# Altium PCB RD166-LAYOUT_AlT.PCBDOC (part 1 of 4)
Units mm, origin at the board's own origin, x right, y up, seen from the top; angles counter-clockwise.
Board outline 88.7 x 59.07 mm, 2 copper layers (TOP, BOTTOM), stack 0 mm thick; 138 components, 120 nets, 706 pads, 0 vias.
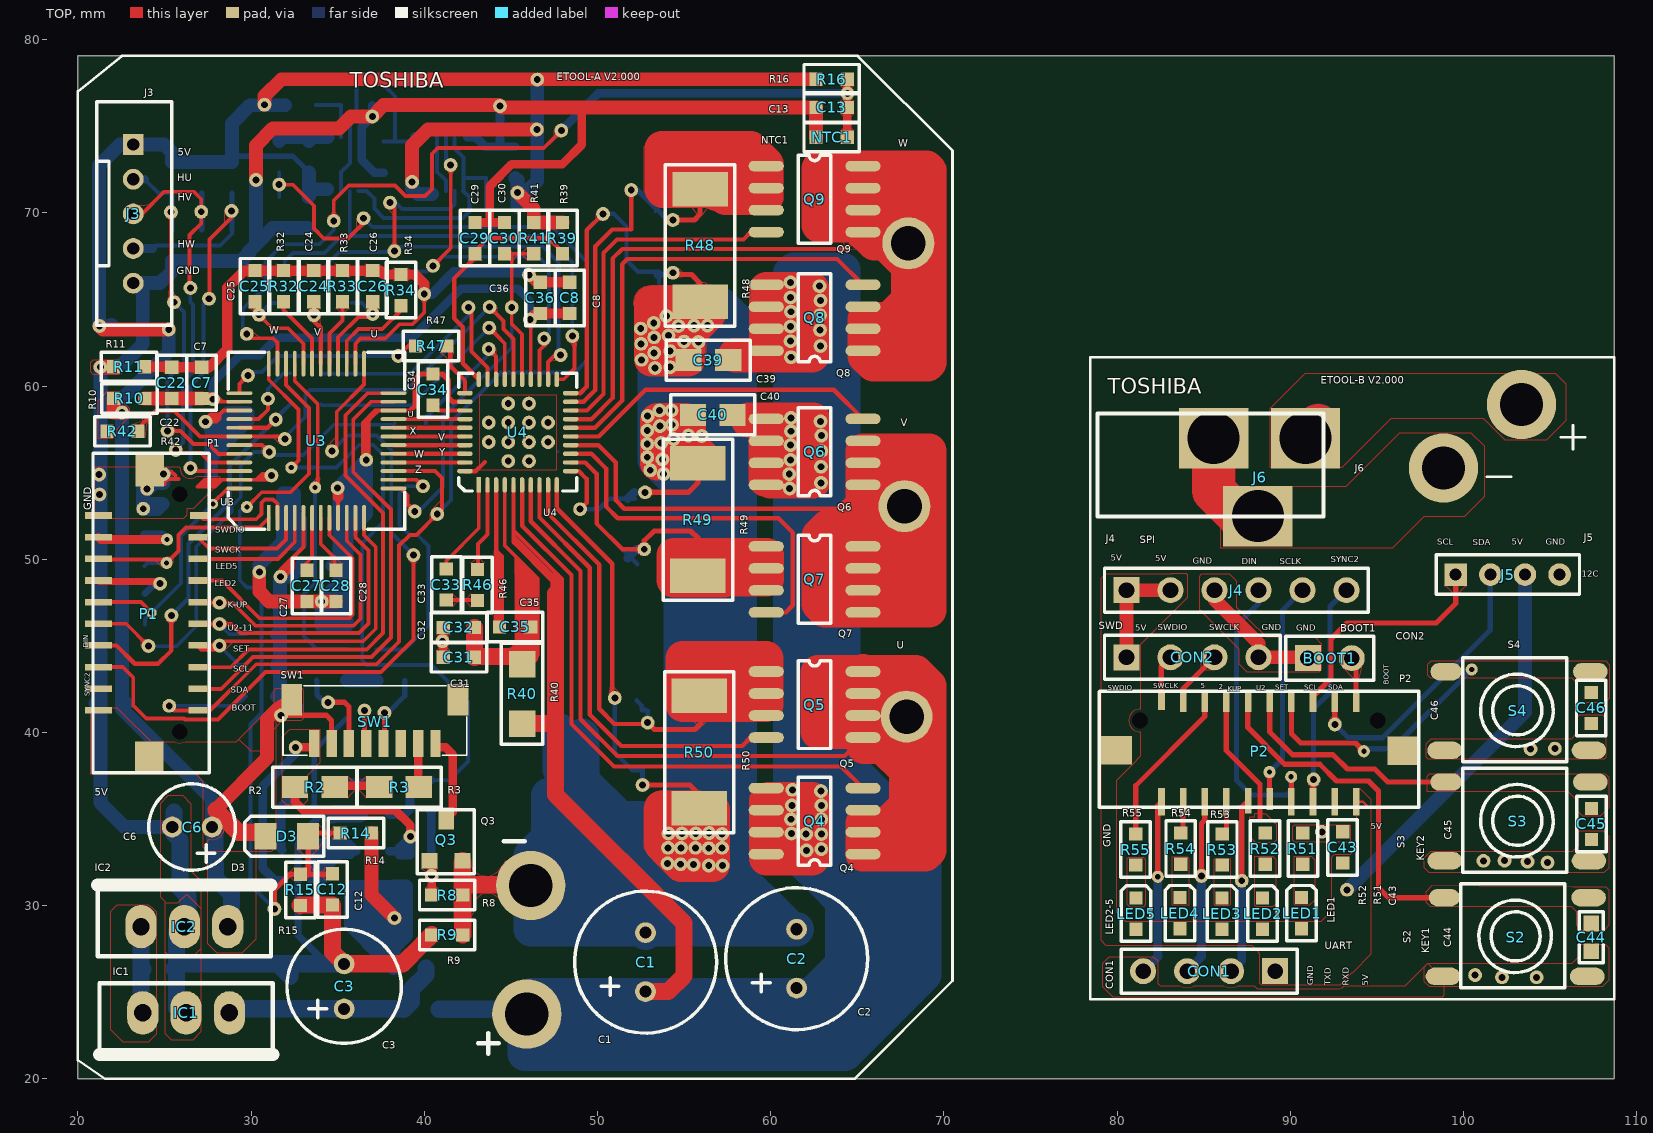
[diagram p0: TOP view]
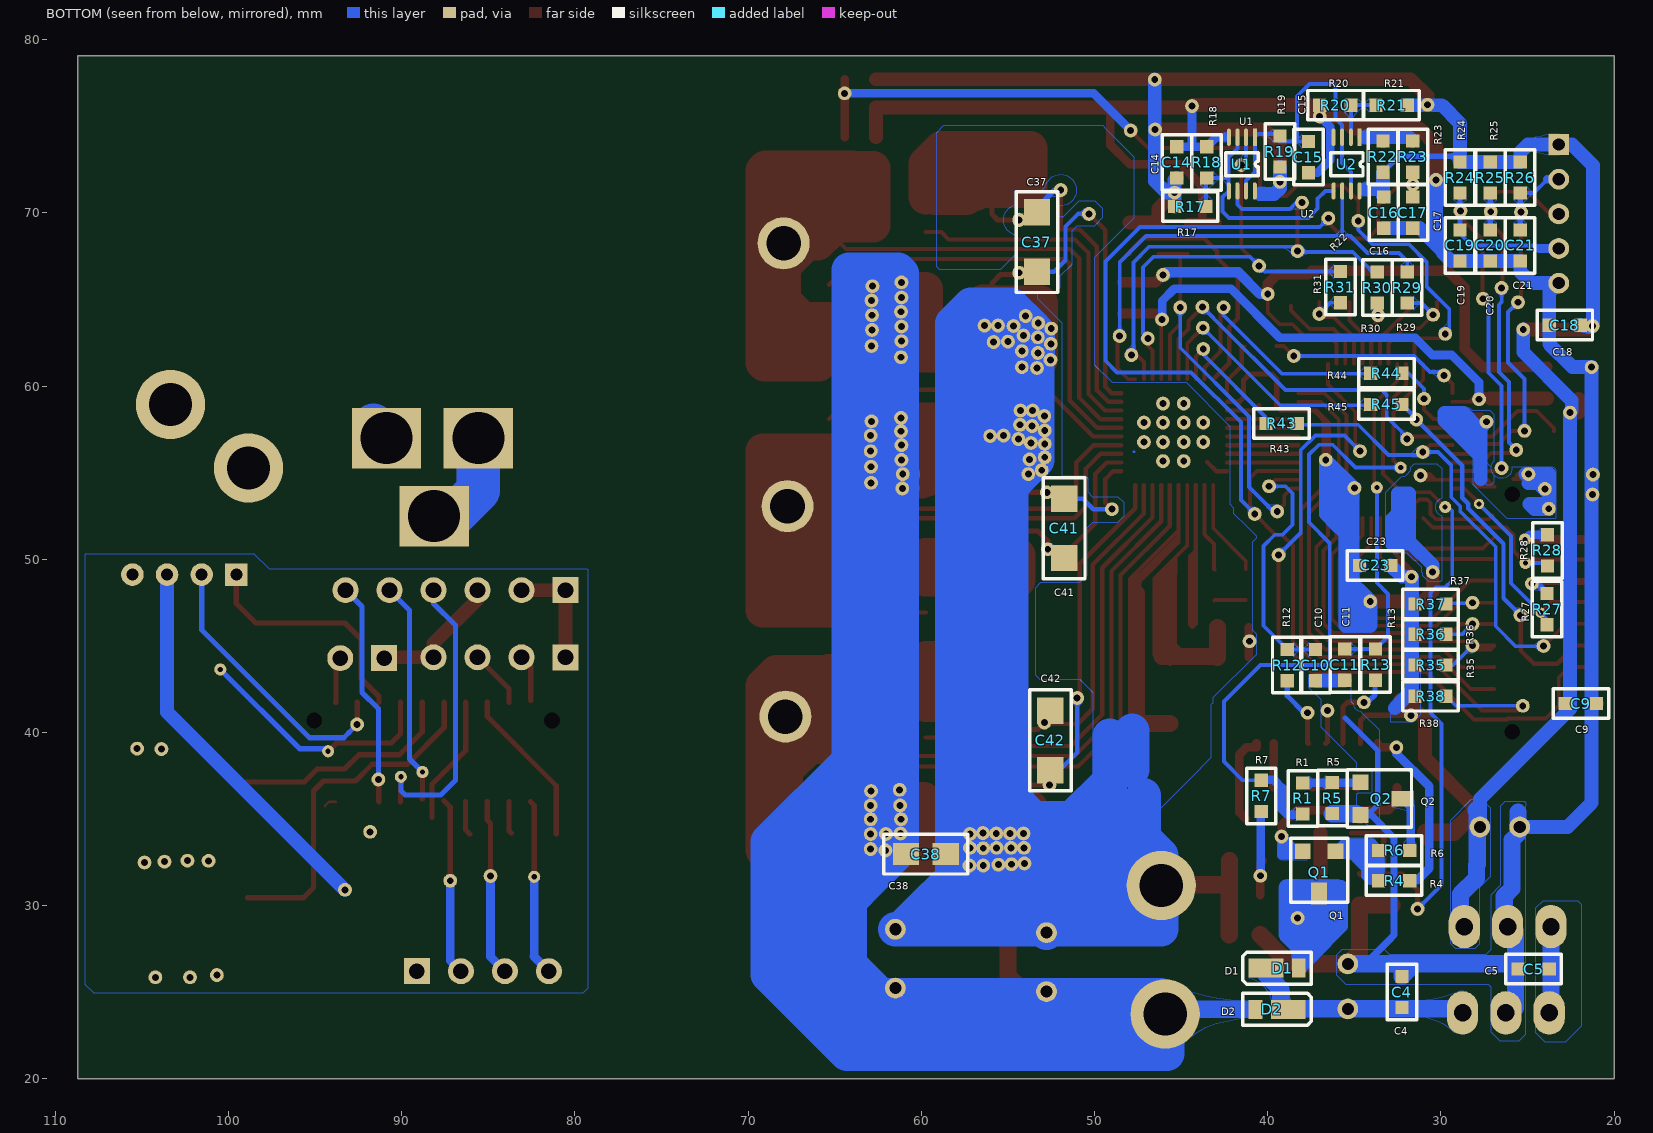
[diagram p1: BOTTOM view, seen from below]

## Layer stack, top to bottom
Top Solder: solder mask 0.0102, Solder Resist, Dk 3.5
TOP: signal copper (thickness not stored)
BOTTOM: signal copper (thickness not stored)
Bottom Solder: solder mask 0.0102, Solder Resist, Dk 3.5

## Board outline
108.7,79.066 108.7,20 20,20 20,79.066

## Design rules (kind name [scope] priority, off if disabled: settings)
AssemblyTestPointUsage [All] p0: scope1count=1 scope1_0_kind=Board scope1_0_value=Board scope2count=1 scope2_0_kind=Board scope2_0_value=Board commentlength=0
AssemblyTestpoint [All] p0: scope1count=1 scope1_0_kind=Board scope1_0_value=Board scope2count=1 scope2_0_kind=Board scope2_0_value=Board commentlength=0
Clearance [All] p0: scope1count=1 scope1_0_kind=Board scope1_0_value=Board scope2count=1 scope2_0_kind=Board scope2_0_value=Board commentlength=0 gap=0.001
Clearance [All] p1: gap=0.001 ignorepadtopadclearanceinfootprint=TRUE except(0.15: Arc-Arc Arc-Track Arc-SMDPad Arc-THPad Arc-Via Arc-Fill Arc-Poly Arc-Region Arc-Text Track-Track Track-SMDPad Track-THPad Track-Via Track-Fill Track-Poly Track-Region Track-Text SMDPad-SMDPad SMDPad-THPad SMDPad-Via SMDPad-Text THPad-THPad THPad-Via THPad-Text Via-Via Via-Fill Via-Poly Via-Region Via-Text Fill-Fill Fill-Poly Fill-Region Fill-Text Poly-Poly Poly-Region Poly-Text Region-Region Region-Text Text-Text; 0.2: SMDPad-Fill SMDPad-Poly SMDPad-Region THPad-Fill THPad-Poly THPad-Region; 0.3: Arc-Hole Track-Hole SMDPad-Hole THPad-Hole Via-Hole Fill-Hole Poly-Hole Region-Hole Text-Hole)
ComponentClearance [All] p0: scope1count=1 scope1_0_kind=Board scope1_0_value=Board scope2count=1 scope2_0_kind=Board scope2_0_value=Board commentlength=0 gap=0.254 collisioncheckmode=3
DiffPairsRouting [All] p0: scope1count=1 scope1_0_kind=Board scope1_0_value=Board scope2count=1 scope2_0_kind=Board scope2_0_value=Board commentlength=0
FabricationTestPointUsage [All] p0: scope1count=1 scope1_0_kind=Board scope1_0_value=Board scope2count=1 scope2_0_kind=Board scope2_0_value=Board commentlength=0 valid=0 allowmultiple=FALSE
FabricationTestpoint [All] p0: scope1count=1 scope1_0_kind=Board scope1_0_value=Board scope2count=1 scope2_0_kind=Board scope2_0_value=Board commentlength=0 side=3 testpointundercomponent=TRUE minsize=1.016 maxsize=2.54 preferedsize=1.524 minholesize=0 maxholesize=1.016 preferedholesize=0.813 testpointgrid=0.025
FanoutControl Fanout_Default [All] p0: scope1count=1 scope1_0_kind=Board scope1_0_value=Board scope2count=1 scope2_0_kind=Board scope2_0_value=Board commentlength=30 // Fanout_Default (Default Rule)
FanoutControl Fanout_Small [All] p0 off: scope1count=1 scope1_0_kind=Board scope1_0_value=Board scope2count=1 scope2_0_kind=Board scope2_0_value=Board commentlength=84 // Protel DXP Scope 1 Expression Was: (CompPinCount < 5)   Fanout_Small (Default Rule)
FanoutControl Fanout_SOIC [All] p0 off: scope1count=1 scope1_0_kind=Board scope1_0_value=Board scope2count=1 scope2_0_kind=Board scope2_0_value=Board commentlength=71 // Protel DXP Scope 1 Expression Was: IsSOIC   Fanout_SOIC (Default Rule)
FanoutControl Fanout_LCC [All] p0 off: scope1count=1 scope1_0_kind=Board scope1_0_value=Board scope2count=1 scope2_0_kind=Board scope2_0_value=Board commentlength=69 // Protel DXP Scope 1 Expression Was: IsLCC   Fanout_LCC (Default Rule)
FanoutControl Fanout_BGA [All] p0 off: scope1count=1 scope1_0_kind=Board scope1_0_value=Board scope2count=1 scope2_0_kind=Board scope2_0_value=Board commentlength=69 // Protel DXP Scope 1 Expression Was: IsBGA   Fanout_BGA (Default Rule)
Height [All] p0: scope1count=1 scope1_0_kind=Board scope1_0_value=Board scope2count=1 scope2_0_kind=Board scope2_0_value=Board commentlength=0
HoleSize [All] p0: scope1count=1 scope1_0_kind=Board scope1_0_value=Board scope2count=1 scope2_0_kind=Board scope2_0_value=Board commentlength=0 absolutevalues=TRUE maxlimit=100 minlimit=0.001 maxpercent=80.000 minpercent=20.000
HoleSize [All] p1: absolutevalues=TRUE maxlimit=100 minlimit=0.001 maxpercent=80.000 minpercent=20.000
HoleToHoleClearance [All] p0: scope1count=1 scope1_0_kind=Board scope1_0_value=Board scope2count=1 scope2_0_kind=Board scope2_0_value=Board commentlength=0
HoleToHoleClearance [All] p1: gap=0.4 allowstackedmicrovias=FALSE
LayerPairs [All] p0: scope1count=1 scope1_0_kind=Board scope1_0_value=Board scope2count=1 scope2_0_kind=Board scope2_0_value=Board commentlength=0 enforce=TRUE
MinimumSolderMaskSliver [All] p0: scope1count=1 scope1_0_kind=Board scope1_0_value=Board scope2count=1 scope2_0_kind=Board scope2_0_value=Board commentlength=0
MinimumSolderMaskSliver [All] p1: minsoldermaskwidth=0.1
NetAntennae [All] p0: scope1count=1 scope1_0_kind=Board scope1_0_value=Board scope2count=1 scope2_0_kind=Board scope2_0_value=Board commentlength=0
NetAntennae [All] p1: netantennaetolerance=100
PasteMaskExpansion [All] p0: scope1count=1 scope1_0_kind=Board scope1_0_value=Board scope2count=1 scope2_0_kind=Board scope2_0_value=Board commentlength=0 expansion=0
PlaneClearance [All] p0: scope1count=1 scope1_0_kind=Board scope1_0_value=Board scope2count=1 scope2_0_kind=Board scope2_0_value=Board commentlength=0 clearance=0.001
PlaneClearance [All] p1: clearance=0.001
PlaneConnect [All] p0: scope1count=1 scope1_0_kind=Board scope1_0_value=Board scope2count=1 scope2_0_kind=Board scope2_0_value=Board commentlength=0 planeconnectstyle=Direct reliefexpansion=0.508 reliefentries=4 reliefconductorwidth=0.254 reliefairgap=0.254
PlaneConnect [All] p1: planeconnectstyle=Direct reliefexpansion=0.508 reliefentries=4 reliefconductorwidth=0.254 reliefairgap=0.254
PolygonConnect [All] p0: scope1count=1 scope1_0_kind=Board scope1_0_value=Board scope2count=1 scope2_0_kind=Board scope2_0_value=Board commentlength=0 connectstyle=Direct reliefconductorwidth=0.254 reliefentries=4 polygonreliefangle="90 Angle"
PolygonConnect [All] p1: connectstyle=Direct reliefconductorwidth=0.254 reliefentries=4 polygonreliefangle="90 Angle" airgapwidth=0.254
RoutingCorners [All] p0: scope1count=1 scope1_0_kind=Board scope1_0_value=Board scope2count=1 scope2_0_kind=Board scope2_0_value=Board commentlength=0 cornerstyle=45-Degree minsetback=2.54 maxsetback=2.54
RoutingLayers [All] p0: scope1count=1 scope1_0_kind=Board scope1_0_value=Board scope2count=1 scope2_0_kind=Board scope2_0_value=Board commentlength=0 top layer=Automatic bottom layer=Automatic
RoutingPriority [All] p0: scope1count=1 scope1_0_kind=Board scope1_0_value=Board scope2count=1 scope2_0_kind=Board scope2_0_value=Board commentlength=0
RoutingTopology [All] p0: scope1count=1 scope1_0_kind=Board scope1_0_value=Board scope2count=1 scope2_0_kind=Board scope2_0_value=Board commentlength=0 topology=Shortest
RoutingVias [All] p0: scope1count=1 scope1_0_kind=Board scope1_0_value=Board scope2count=1 scope2_0_kind=Board scope2_0_value=Board commentlength=0 holewidth=0.1 width=0.1 viastyle="Through Hole" minholewidth=0.001 minwidth=0.001 maxholewidth=100 maxwidth=100
RoutingVias [All] p1: holewidth=0.1 width=0.1 viastyle="Through Hole" minholewidth=0.001 minwidth=0.001 maxholewidth=100 maxwidth=100
ShortCircuit [All] p0: scope1count=1 scope1_0_kind=Board scope1_0_value=Board scope2count=1 scope2_0_kind=Board scope2_0_value=Board commentlength=0 allowed=FALSE
ShortCircuit [All] p0: scope1count=1 scope1_0_kind=Board scope1_0_value=Board scope2count=1 scope2_0_kind=Board scope2_0_value=Board commentlength=0 allowed=FALSE
SilkToBoardRegionClearance [All] p0: scope1count=1 scope1_0_kind=Board scope1_0_value=Board scope2count=1 scope2_0_kind=Board scope2_0_value=Board commentlength=0
SilkToSilkClearance [All] p0: scope1count=1 scope1_0_kind=Board scope1_0_value=Board scope2count=1 scope2_0_kind=Board scope2_0_value=Board commentlength=0
SilkToSilkClearance [All] p1: silktosilkclearance=0.001
SilkToSolderMaskClearance [All] p0 off: scope1count=1 scope1_0_kind=Board scope1_0_value=Board scope2count=1 scope2_0_kind=Board scope2_0_value=Board commentlength=44 // Protel DXP Scope 1 Expression Was: IsPad
SilkToSolderMaskClearance [IsPad] p1: minsilkscreentomaskgap=0 clearancetoexposedcopper=TRUE
SolderMaskExpansion [All] p0: scope1count=1 scope1_0_kind=Board scope1_0_value=Board scope2count=1 scope2_0_kind=Board scope2_0_value=Board commentlength=0 expansion=0.001
SolderMaskExpansion [All] p1: expansion=0.001
UnRoutedNet [All] p0: scope1count=1 scope1_0_kind=Board scope1_0_value=Board scope2count=1 scope2_0_kind=Board scope2_0_value=Board commentlength=0
UnpouredPolygon [All] p0: scope1count=1 scope1_0_kind=Board scope1_0_value=Board scope2count=1 scope2_0_kind=Board scope2_0_value=Board commentlength=0
Width [All] p0: scope1count=1 scope1_0_kind=Board scope1_0_value=Board scope2count=1 scope2_0_kind=Board scope2_0_value=Board commentlength=0 maxlimit=1000 minlimit=2539.975 preferedwidth=0
Width [All] p1: maxlimit=1000 minlimit=2539.975 preferedwidth=0 toplayer_minwidth=0 bottomlayer_minwidth=0 minimp=50.000000 maximp=50.000000 favimp=50.000000
22 further rules are at their usual default settings.

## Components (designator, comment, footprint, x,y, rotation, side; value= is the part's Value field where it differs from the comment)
BOOT1 "HDR1X2" HDR1X2 91.01,44.291 r0 top
C1 "RB_2_3" RB_2_3 52.775,26.741 r90 top
C2 "RB_2_3" RB_2_3 61.5,26.941 r90 top
C3 "RB_13_25" RB_13_25 35.375,25.341 r90 top
C4 "0603-1_bk" 0603-1_bk 32.25,25.016 r270 bottom
C5 "0603-1_bk" 0603-1_bk 24.65,26.341 r180 bottom
C6 "RB_1_2" RB_1_2 26.6,34.541 r180 top
C7 "0603-1" 0603-1 27.15,60.191 r90 top
C8 "0603-1" 0603-1 48.4,65.091 r90 top
C9 "0603-1_bk" 0603-1_bk 21.925,41.666 r0 bottom
C10 "0603-1_bk" 0603-1_bk 37.25,43.891 r90 bottom
C11 "0603-1_bk" 0603-1_bk 35.55,43.916 r90 bottom
C12 "0603-1" 0603-1 34.7,30.941 r270 top
C13 "0603-1" 0603-1 63.525,76.091 r180 top
C14 "0603-1_bk" 0603-1_bk 45.25,72.916 r90 bottom
C15 "0603-1_bk" 0603-1_bk 37.65,73.216 r90 bottom
C16 "0603-1_bk" 0603-1_bk 33.3,70.016 r270 bottom
C17 "0603-1_bk" 0603-1_bk 31.625,70.016 r90 bottom
C18 "0603-1_bk" 0603-1_bk 22.85,63.516 r180 bottom
C19 "0603-1_bk" 0603-1_bk 28.9,68.116 r90 bottom
C20 "0603-1_bk" 0603-1_bk 27.15,68.116 r90 bottom
C21 "0603-1_bk" 0603-1_bk 25.425,68.116 r90 bottom
C22 "0603-1" 0603-1 25.425,60.191 r270 top
C23 "0603-1_bk" 0603-1_bk 33.8,49.641 r180 bottom
C24 "0603-1" 0603-1 33.625,65.766 r90 top
C25 "0603-1" 0603-1 30.225,65.766 r90 top
C26 "0603-1" 0603-1 37.025,65.766 r90 top
C27 "0603-1" 0603-1 33.225,48.466 r270 top
C28 "0603-1" 0603-1 34.9,48.466 r270 top
C29 "0603-1" 0603-1 42.925,68.541 r90 top
C30 "0603-1" 0603-1 44.625,68.541 r90 top
C31 "0603-1" 0603-1 42,44.341 r180 top
C32 "0603-1" 0603-1 42,46.066 r180 top
C33 "0603-1" 0603-1 41.275,48.541 r90 top
C34 "0603-1" 0603-1 40.5,59.791 r90 top
C35 "0603-1" 0603-1 45.25,46.091 r180 top
C36 "0603-1" 0603-1 46.7,65.091 r90 top
C37 "1206_bk" 1206_bk 53.325,68.316 r270 bottom
C38 "0805_bk" 0805_bk 59.743,32.978 r180 bottom
C39 "0805" 0805 56.4,61.492 r180 top
C40 "0805" 0805 56.657,58.341 r180 top
C41 "1206_bk" 1206_bk 51.75,51.79 r90 bottom
C42 "1206_bk" 1206_bk 52.55,39.541 r270 bottom
C43 "0603-1" 0603-1 93.025,33.366 r270 top
C44 "R0603" R0603 107.373,28.973 r270 top
C45 "0603-1" 0603-1 107.4,34.716 r270 top
C46 "0603-1" 0603-1 107.375,41.416 r270 top
CON1 "HDR1X4" HDR1X4 89.125,26.216 r180 top
CON2 "HDR1X4" HDR1X4 80.545,44.341 r0 top
D1 "D-0805-2_bk" D-0805-2_bk 40.1,26.391 r180 bottom
D2 "D-0805-2_bk" D-0805-2_bk 38.814,24.016 r0 bottom
D3 "D-0805-1" D-0805-1 32.053,34.016 r180 top
IC1 "TO-220" TO-220 28.75,23.816 r180 top
IC2 "TO-220" TO-220 23.65,28.791 r0 top
J3 "SSIP5-4" SSIP5-4 23.2,73.941 r270 top
J4 "HDR1X6" HDR1X6 80.545,48.216 r0 top
J5 "HDR1X4-2" HDR1X4-2 99.55,49.116 r0 top
J6 "J-3PIN" J-3PIN 90.875,56.991 r270 top
LED1 "D-0603-2" D-0603-2 90.65,29.566 r90 top
LED2 "D-0603-2" D-0603-2 88.4,29.541 r90 top
LED3 "D-0603-2" D-0603-2 86.05,29.541 r90 top
LED4 "D-0603-2" D-0603-2 83.625,29.566 r90 top
LED5 "D-0603-2" D-0603-2 81.1,29.541 r90 top
NTC1 "0603-1" 0603-1 63.525,74.366 r0 top
P1 "PCBCOMPONENT_1" PCBCOMPONENT_1 21.187,52.526 r270 top
P2 "PCBCOMPONENT_2" PCBCOMPONENT_2 82.565,36.003 r0 top
Q1 "SOT-23_bk" SOT-23_bk 36.084,33.139 r180 bottom
Q2 "SOT-23_bk" SOT-23_bk 34.65,37.133 r90 bottom
Q3 "SOT-23" SOT-23 40.307,32.591 r0 top
Q4 "SO-8" SO-8 65.331,32.978 r180 top
Q5 "SO-8" SO-8 59.743,43.519 r0 top
Q6 "SO-8" SO-8 65.331,54.291 r180 top
Q7 "SO-8" SO-8 59.743,50.741 r0 top
Q8 "SO-8" SO-8 65.331,62.035 r180 top
Q9 "SO-8" SO-8 59.743,72.703 r0 top
R1 "0603-1_bk" 0603-1_bk 37.975,36.191 r90 bottom
R2 "0805" 0805 33.682,36.841 r0 top
R3 "0805" 0805 38.55,36.841 r0 top
R4 "0603-1_bk" 0603-1_bk 32.7,31.441 r0 bottom
R5 "0603-1_bk" 0603-1_bk 36.275,36.216 r270 bottom
R6 "0603-1_bk" 0603-1_bk 32.7,33.191 r0 bottom
R7 "0603-1_bk" 0603-1_bk 40.375,36.341 r90 bottom
R8 "0603-1" 0603-1 41.325,30.616 r0 top
R9 "0603-1" 0603-1 41.325,28.316 r180 top
R10 "0603-1" 0603-1 22.975,59.291 r0 top
R11 "0603-1" 0603-1 22.95,61.116 r0 top
R12 "0603-1_bk" 0603-1_bk 38.875,43.891 r270 bottom
R13 "0603-1_bk" 0603-1_bk 33.775,43.916 r270 bottom
R14 "0603-1" 0603-1 36.05,34.191 r0 top
R15 "0603-1" 0603-1 32.85,30.916 r90 top
R16 "0603-1" 0603-1 63.525,77.716 r0 top
R17 "0603-1_bk" 0603-1_bk 44.475,70.366 r180 bottom
R18 "0603-1_bk" 0603-1_bk 43.525,72.916 r270 bottom
R19 "0603-1_bk" 0603-1_bk 39.3,73.541 r270 bottom
R20 "0603-1_bk" 0603-1_bk 36.1,76.216 r180 bottom
R21 "0603-1_bk" 0603-1_bk 32.85,76.216 r180 bottom
R22 "0603-1_bk" 0603-1_bk 33.35,73.241 r90 bottom
R23 "0603-1_bk" 0603-1_bk 31.625,73.241 r270 bottom
R24 "0603-1_bk" 0603-1_bk 28.9,72.041 r270 bottom
R25 "0603-1_bk" 0603-1_bk 27.15,72.041 r270 bottom
R26 "0603-1_bk" 0603-1_bk 25.425,72.041 r270 bottom
R27 "0603-1_bk" 0603-1_bk 23.875,47.116 r90 bottom
R28 "0603-1_bk" 0603-1_bk 23.85,50.516 r90 bottom
R29 "0603-1_bk" 0603-1_bk 31.95,65.691 r90 bottom
R30 "0603-1_bk" 0603-1_bk 33.675,65.691 r270 bottom
R31 "0603-1_bk" 0603-1_bk 35.8,65.716 r270 bottom
R32 "0603-1" 0603-1 31.875,65.766 r270 top
R33 "0603-1" 0603-1 35.275,65.766 r270 top
R34 "0603-1" 0603-1 38.65,65.541 r270 top
R35 "0603-1_bk" 0603-1_bk 30.6,43.891 r180 bottom
R36 "0603-1_bk" 0603-1_bk 30.6,45.666 r180 bottom
R37 "0603-1_bk" 0603-1_bk 30.6,47.416 r180 bottom
R38 "0603-1_bk" 0603-1_bk 30.6,42.091 r0 bottom
R39 "0603-1" 0603-1 47.975,68.541 r270 top
R40 "1206" 1206 45.65,42.23 r270 top
R41 "0603-1" 0603-1 46.325,68.541 r90 top
R42 "0603-1" 0603-1 22.575,57.391 r180 top
R43 "0603-1_bk" 0603-1_bk 39.2,57.841 r180 bottom
R44 "0603-1_bk" 0603-1_bk 33.15,60.741 r180 bottom
R45 "0603-1_bk" 0603-1_bk 33.15,58.941 r180 bottom
R46 "0603-1" 0603-1 43.075,48.516 r90 top
R47 "0603-1" 0603-1 40.4,62.316 r0 top
R48 "2512" 2512 55.925,68.116 r270 top
R49 "2512" 2512 55.8,52.291 r90 top
R50 "2512" 2512 55.875,38.866 r270 top
R51 "0603-1" 0603-1 90.725,33.291 r90 top
R52 "0603-1" 0603-1 88.55,33.291 r90 top
R53 "0603-1" 0603-1 86.075,33.241 r90 top
R54 "0603-1" 0603-1 83.675,33.291 r90 top
R55 "0603-1" 0603-1 81.075,33.241 r90 top
S2 "DOT6X6SMT" DOT6X6SMT 98.895,30.461 r0 top
S3 "DOT6X6SMT" DOT6X6SMT 98.995,37.136 r0 top
S4 "DOT6X6SMT" DOT6X6SMT 98.995,43.511 r0 top
SW1 "SH1_0_SMD_8" SH1_0_SMD_8 33.65,39.366 r0 top
U1 "SSOP8-0_5_bk" SSOP8-0_5_bk 40.75,74.366 r90 bottom
U2 "SSOP8-0_5_bk" SSOP8-0_5_bk 34.7,74.366 r90 bottom
U3 "LQFP-48" LQFP-48 31.025,52.391 r90 top
U4 "QFN-40" QFN-40 43.15,54.291 r90 top

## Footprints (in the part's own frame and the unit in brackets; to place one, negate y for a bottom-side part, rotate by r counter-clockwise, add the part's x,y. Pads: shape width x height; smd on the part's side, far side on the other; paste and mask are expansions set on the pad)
0603-1 [mil] "KC00080BKP"
  rect 30x30 smd paste-37.87 mask+0: 1(-35.43,0) 2(35.43,0)
  silkscreen extent -63,-33 63,33
0603-1_bk [mil] "KC00080BKP"
  rect 30x30 smd paste-37.87 mask+0: 1(35.43,0) 2(-35.43,0)
  silkscreen extent -63,-33 63,33
0805 [mil] "KC00080BKP"
  rect 60x50 smd paste-67.87 mask+0: 1(-45,0.02) 2(45,0.02)
  silkscreen extent -95,-45 95,45
0805_bk [mil] "KC00080BKP"
  rect 60x50 smd paste-67.87 mask+0: 1(45,-0.02) 2(-45,-0.02)
  silkscreen extent -95,-45 95,45
1206 [mil] "KC00080BKP"
  rect 60x60 smd paste-67.87 mask+0: 1(-67.52,0) 2(67.52,0)
  silkscreen extent -115,-47 115,47
1206_bk [mil] "KC00080BKP"
  rect 60x60 smd paste-67.87 mask+0: 1(67.52,0) 2(-67.52,0)
  silkscreen extent -115,-47 115,47
2512 [mm] "KC00080BKP"
  rect 2x3.2 smd paste-3.4 mask+0: 1(-3.25,0) 2(3.25,0)
  silkscreen extent -4.65,-2 4.65,2
D-0603-2 [mil] "KC00080BKP"
  rect 30x30 smd paste-37.87 mask+0: A(-35.43,0) K(35.43,0)
  silkscreen extent -63,-33 63,33
D-0805-1 [mil] "KC00080BKP"
  rect 50x60 smd paste-67.87 mask+0: 1(-48.09,0) 2(48.09,0)
  silkscreen extent -84,-45 96,45
D-0805-2_bk [mm] "KC00080BKP"
  rect 2x1.1 smd paste-2.2 mask+0: 1(0,0)
  rect 0.8x1.1 smd paste-1.3 mask+0: 2(1.886,0)
  silkscreen extent -1.33,-0.93 2.62,0.93
DOT6X6SMT [mm] "KC00080BKP"
  oval 1.8x1 smd paste-2 mask+0: 1(0,0)
  oval 2x1 smd paste-2.2 mask+0: 2(-0.08,-4.54) 3(8.25,-4.54) 4(8.33,0)
  silkscreen extent 0.96,-5.21 6.96,0.79
HDR1X2 [mm] "KC00080BKP"
  rect 1.5x1.5 / inner round 0 / far side rect 1.5x1.5 hole 0.9 paste-1.7 mask+0: 1(0,0)
  round 1.5 / inner round 0 / far side round 1.5 hole 0.9 paste-1.7 mask+0: 2(2.54,0)
  silkscreen extent -1.27,-1.27 3.81,1.27
HDR1X4 [mm] "KC00080BKP"
  rect 1.5x1.5 / inner round 0 / far side rect 1.5x1.5 hole 0.9 paste-1.7 mask+0: 1(0,0)
  round 1.5 / inner round 0 / far side round 1.5 hole 0.9 paste-1.7 mask+0: 2(2.54,0) 3(5.08,0) 4(7.62,0)
  silkscreen extent -1.27,-1.27 8.89,1.27
HDR1X4-2 [mm] "KC00080BKP"
  rect 1.3x1.3 / inner round 0 / far side rect 1.3x1.3 hole 0.7 paste-1.5 mask+0: 1(0,0)
  round 1.3 / inner round 0 / far side round 1.3 hole 0.7 paste-1.5 mask+0: 2(2,0) 3(4,0) 4(6,0)
  silkscreen extent -1.12,-1.13 7.15,1.15
HDR1X6 [mm] "KC00080BKP"
  rect 1.5x1.5 / inner round 0 / far side rect 1.5x1.5 hole 0.9 paste-1.7 mask+0: 1(0,0)
  round 1.5 / inner round 0 / far side round 1.5 hole 0.9 paste-1.7 mask+0: 2(2.54,0) 3(5.08,0) 4(7.62,0) 5(10.16,0) 6(12.7,0)
  silkscreen extent -1.27,-1.27 13.97,1.27
J-3PIN [mm] "KC00080BKP"
  rect 3.5x4 / inner round 0 / far side rect 3.5x4 hole 3 paste-4.2 mask+0: 1(0,0) 2(0,-5.3) 3(4.5,-2.75)
  silkscreen extent -1.42,-12 4.52,1.05
LQFP-48 [mm] "KC00080BKP"
  rect 1.5x0.22 smd paste-1.7 mask+0: 1(0,0)
  oval 1.5x0.22 smd paste-1.7 mask+0: 2(0,-0.5) 3(0,-1) 4(0,-1.5) 5(0,-2) 6(0,-2.5) 7(0,-3) 8(0,-3.5) 9(0,-4) 10(0,-4.5) 11(0,-5) 12(0,-5.5) 25(8.9,-5.5) 26(8.9,-5) 27(8.9,-4.5) 28(8.9,-4) 29(8.9,-3.5) 30(8.9,-3) 31(8.9,-2.5) 32(8.9,-2) 33(8.9,-1.5) 34(8.9,-1) 35(8.9,-0.5) 36(8.9,0)
  oval 0.22x1.5 smd paste-1.7 mask+0: 13(1.7,-7.2) 14(2.2,-7.2) 15(2.7,-7.2) 16(3.2,-7.2) 17(3.7,-7.2) 18(4.2,-7.2) 19(4.7,-7.2) 20(5.2,-7.2) 21(5.7,-7.2) 22(6.2,-7.2) 23(6.7,-7.2) 24(7.2,-7.2) 37(7.2,1.7) 38(6.7,1.7) 39(6.2,1.7) 40(5.7,1.7) 41(5.2,1.7) 42(4.7,1.7) 43(4.2,1.7) 44(3.7,1.7) 45(3.2,1.7) 46(2.7,1.7) 47(2.2,1.7) 48(1.7,1.7)
  silkscreen extent -0.65,-7.85 9.55,2.35
PCBCOMPONENT_1 [mil] "KC00080BKP"
  rect 15x62.01 smd paste-69.88 mask+0: 1(442.91,0) 2(393.7,0) 3(344.49,0) 4(295.28,0) 5(246.06,0) 6(196.85,0) 7(147.64,0) 8(98.43,0) 9(49.21,0) 10(0,0)
  rect 15x43.31 smd paste-51.18 mask+0: 11(442.91,225.91) 12(393.7,225.91) 13(344.49,225.91) 14(295.28,225.91) 15(246.06,225.91) 16(196.85,225.91) 17(147.64,225.91) 18(98.43,225.91) 19(49.21,225.91) 20(0,229.84)
  rect 70.87x64.96 smd paste-78.74 mask+0: 21(548.62,115.67) 22(-101.97,116.65)
  round 3.94 / inner round 0 / far side round 3.94 hole 35.43 unplated paste-43.31 mask+0: 23(491.77,184.57) 24(-48.82,184.57)
  silkscreen extent -141,-12 585,252
PCBCOMPONENT_2 [mm] "KC00080BKP"
  rect 0.381x1.575 smd paste-1.775 mask+0: 1(11.25,0) 2(10,0) 3(8.75,0) 4(7.5,0) 7(3.75,0) 8(2.5,0) 9(1.25,0) 10(0,0)
  rect 0.381x1.275 smd paste-1.475 mask+0: 5(6.25,0.15)
  rect 0.381x1.453 smd paste-1.653 mask+0: 6(5,0.06)
  rect 0.381x1.1 smd paste-1.3 mask+0: 11(11.25,5.738) 12(10,5.738) 13(8.75,5.738) 14(7.5,5.738) 15(6.25,5.738) 16(5,5.738) 17(3.75,5.738) 18(2.5,5.738) 19(1.25,5.738) 20(0,5.838)
  rect 1.8x1.65 smd paste-2 mask+0: 21(13.935,2.938) 22(-2.59,2.963)
  round 0.1 / inner round 0 / far side round 0.1 hole 0.9 unplated paste-1.1 mask+0: 23(12.491,4.688) 24(-1.24,4.688)
  silkscreen extent -3.59,-0.31 14.86,6.39
QFN-40 [mm] "KC00080BKP"
  rect 0.9x0.25 smd paste-1.1 mask+0: 1(0,0)
  oval 0.9x0.25 smd paste-1.1 mask+0: 2(0,-0.5) 3(0,-1) 4(0,-1.5) 5(0,-2) 6(0,-2.5) 7(0,-3) 8(0,-3.5) 9(0,-4) 10(0,-4.5) 21(6.1,-4.5) 22(6.1,-4) 23(6.1,-3.5) 24(6.1,-3) 25(6.1,-2.5) 26(6.1,-2) 27(6.1,-1.5) 28(6.1,-1) 29(6.1,-0.5) 30(6.1,0)
  oval 0.25x0.9 smd paste-1.1 mask+0: 11(0.8,-5.3) 12(1.3,-5.3) 13(1.8,-5.3) 14(2.3,-5.3) 15(2.8,-5.3) 16(3.3,-5.3) 17(3.8,-5.3) 18(4.3,-5.3) 19(4.8,-5.3) 20(5.3,-5.3) 31(5.3,0.8) 32(4.8,0.8) 33(4.3,0.8) 34(3.8,0.8) 35(3.3,0.8) 36(2.8,0.8) 37(2.3,0.8) 38(1.8,0.8) 39(1.3,0.8) 40(0.8,0.8)
  silkscreen extent -0.35,-5.65 6.45,1.15
R0603 [mm] "KC00080BKP"
  rect 0.9x0.9 smd paste-1.1 mask+0: 1(0,0) 2(1.6,0)
  silkscreen extent -0.68,-0.7 2.28,0.7
RB_1_2 [mm] "KC00080BKP"
  round 1.2 / inner round 0 / far side round 1.2 hole 0.7 paste-1.4 mask+0: 1(-1.15,0) 2(1.15,0)
  silkscreen extent -2.5,-2.5 2.5,2.5
RB_2_3 [mm] "KC00080BKP"
  round 1.2 / inner round 0 / far side round 1.2 hole 0.7 paste-1.4 mask+0: 1(-1.7,0) 2(1.7,0)
  silkscreen extent -4.1,-4.1 4.1,4.1
RB_13_25 [mm] "KC00080BKP"
  round 1.2 / inner round 0 / far side round 1.2 hole 0.7 paste-1.4 mask+0: 1(-1.3,0) 2(1.3,0)
  silkscreen extent -3.3,-3.3 3.3,3.3
SH1_0_SMD_8 [mm] "KC00080BKP"
  rect 0.6x1.55 smd paste-1.75 mask+0: 1(0,0) 2(1,0) 3(2,0) 4(3,0) 5(4,0) 6(5,0) 7(6,0) 8(7,0)
  rect 1.2x1.8 smd paste-2 mask+0: 9(8.3,2.525) 10(-1.3,2.525)
  silkscreen extent -1.8,-0.67 8.8,3.33
SO-8 [mil] "KC00080BKP"
  oval 80x24.02 smd paste-87.87 mask+0: 1(0,0) 2(0,-50) 3(0,-100) 4(0,-150) 5(220,-150) 6(220,-100) 7(220,-50) 8(220,0)
  silkscreen extent 73,-175 147,25
SOT-23 [mm] "KC00080BKP"
  rect 0.91x0.91 smd paste-1.11 mask+0: B(0,0) E(1.9,0)
  rect 0.91x1.27 smd paste-1.47 mask+0: C(0.958,2.43)
  silkscreen extent -0.71,-0.75 2.59,2.95
SOT-23_bk [mm] "KC00080BKP"
  rect 0.91x0.91 smd paste-1.11 mask+0: B(0,0) E(-1.9,0)
  rect 0.91x1.27 smd paste-1.47 mask+0: C(-0.958,-2.43)
  silkscreen extent -2.59,-2.95 0.71,0.75
SSIP5-4 [mm] "KC00080BKP"
  rect 1.2x1.2 / inner round 0 / far side rect 1.2x1.2 hole 0.7 paste-1.4 mask+0: 1(0,0)
  round 1.2 / inner round 0 / far side round 1.2 hole 0.7 paste-1.4 mask+0: 2(2,0) 3(4,0) 4(6,0) 5(8,0)
  silkscreen extent -2.47,-2.1 10.42,2.23
SSOP8-0_5_bk [mm] "KC00080BKP"
  rect 1x0.23 smd paste-1.2 mask+0: 1(0,0)
  oval 1x0.23 smd paste-1.2 mask+0: 2(0,0.5) 3(0,1) 4(0,1.5) 5(-3.1,1.5) 6(-3.1,1) 7(-3.1,0.5) 8(-3.1,0)
  silkscreen extent -2.22,-0.2 -0.88,1.68
TO-220 [mm] "KC00080BKP"
  oval 1.8x2.5 / inner round 0 / far side oval 1.8x2.5 hole 1 paste-2.7 mask+0: 1(0,0) 2(2.5,0) 3(5,0)
  silkscreen extent -2.5,-1.7 7.5,2.4

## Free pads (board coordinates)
  round 0.8 / inner round 0 / far side round 0.8 hole 0.4 paste-0.8 mask+0: ""(21.225,54.891) ""(21.25,63.466) ""(21.25,53.741) ""(21.3,61.091) ""(22.55,58.466) ""(23.775,52.916) ""(24,54.066) ""(24.075,44.991) ""(24.751,48.59) ""(24.95,54.916) ""(25.176,57.415) ""(25.25,63.266) ""(25.276,41.54) ""(25.375,70.041) ""(25.401,46.765) ""(25.55,64.841) ""(25.651,56.315) ""(26.5,65.666) ""(26.501,55.265) ""(27.125,70.066) ""(27.375,57.941) ""(27.575,65.041) ""(27.8,59.241) ""(28.176,45.015) ""(28.176,47.49) ""(28.18,46.265) ""(28.875,70.116) ""(29.75,63.016) ""(29.825,60.616) ""(30.287,71.903) ""(30.45,64.116) ""(30.476,49.265) ""(30.775,76.241) ""(30.975,59.266) ""(31.05,56.191) ""(31.176,54.84) ""(31.351,29.815) ""(31.425,58.066) ""(31.625,71.628) ""(31.701,48.99) ""(31.735,40.991) ""(31.951,56.94) ""(32.575,39.141) ""(33.625,64.091) ""(34.084,47.565) ""(34.451,41.742) ""(34.675,56.241) ""(34.775,69.541) ""(35,54.116) ""(36.5,69.691) ""(36.551,41.265) ""(36.65,55.743) ""(37,75.566) ""(37.025,64.166) ""(37.701,41.14) ""(38.025,70.591) ""(38.275,67.791) ""(38.276,29.29) ""(38.5,61.741) ""(39.201,33.99) ""(39.3,71.791) ""(39.375,50.241) ""(39.451,52.765) ""(39.925,54.216) ""(40,65.316) ""(40.426,31.726) ""(40.5,66.941) ""(40.75,52.616) ""(41.05,45.266) ""(41.525,72.766) ""(42.551,64.54) ""(43.725,56.766) ""(43.725,57.891) ""(43.725,62.141) ""(43.75,63.366) ""(43.776,64.565) ""(44.375,76.166) ""(44.85,55.666) ""(44.85,56.766) ""(44.85,57.891) ""(44.85,58.991) ""(45.05,64.541) ""(45.375,71.166) ""(46.05,55.666) ""(46.05,56.766) ""(46.05,57.891) ""(46.05,58.991) ""(46.05,66.416) ""(46.1,63.841) ""(46.5,74.816) ""(46.525,77.691) ""(46.925,62.741) ""(47.15,56.766) ""(47.15,57.891) ""(47.876,61.79) ""(47.912,74.753) ""(48.551,62.89) ""(49.001,52.89) ""(50.325,69.941) ""(51.001,41.99) ""(51.951,71.315) ""(52.5,63.316) ""(52.525,62.441) ""(52.55,61.516) ""(52.6,36.966) ""(52.701,50.578) ""(52.75,53.866) ""(52.875,55.891) ""(52.875,56.666) ""(52.875,57.441) ""(52.9,40.566) ""(52.9,58.266) ""(53.05,55.141) ""(53.25,63.641) ""(53.275,61.916) ""(53.275,62.816) ""(53.325,61.041) ""(53.575,58.591) ""(53.6,57.691) ""(53.675,56.716) ""(53.75,55.766) ""(53.825,54.916) ""(53.975,64.041) ""(54.05,32.441) ""(54.075,33.341) ""(54.1,34.166) ""(54.1,62.916) ""(54.2,61.091) ""(54.2,62.016) ""(54.275,58.591) ""(54.3,57.766) ""(54.35,66.541) ""(54.35,69.591) ""(54.4,56.941) ""(54.675,63.466) ""(54.8,32.391) ""(54.825,33.341) ""(54.875,34.166) ""(55,62.566) ""(55.25,57.141) ""(55.55,32.366) ""(55.575,63.491) ""(55.65,33.341) ""(55.675,34.166) ""(55.825,62.541) ""(56.025,57.116) ""(56.35,63.491) ""(56.425,32.316) ""(56.425,33.316) ""(56.45,34.191) ""(57.2,33.341) ""(57.2,34.141) ""(57.225,32.316) ""(61.075,54.916) ""(61.1,54.091) ""(61.15,55.741) ""(61.15,56.591) ""(61.15,62.591) ""(61.15,63.441) ""(61.15,65.116) ""(61.15,65.991) ""(61.175,34.991) ""(61.175,57.391) ""(61.175,58.166) ""(61.175,61.666) ""(61.175,64.291) ""(61.2,34.166) ""(61.225,35.791) ""(61.25,36.691) ""(62.05,34.141) ""(62.075,33.191) ""(62.825,65.766) ""(62.85,63.241) ""(62.85,64.091) ""(62.875,57.966) ""(62.875,62.316) ""(62.875,64.941) ""(62.9,36.616) ""(62.9,54.416) ""(62.9,55.341) ""(62.925,33.266) ""(62.925,34.141) ""(62.925,34.991) ""(62.925,35.791) ""(62.925,56.241) ""(62.925,57.141) ""(64.425,76.903) ""(84.875,31.716) ""(87.2,31.441) ""(91.351,37.29) ""(91.823,34.266) ""(92.575,40.466) ""(93.275,30.916) ""(100.675,25.991) ""(101.15,32.591) ""(102.225,25.866) ""(102.375,32.598) ""(103.7,32.541) ""(103.875,39.041) ""(104.225,25.866) ""(104.85,32.491) ""(105.275,39.066)
  round 0.6 / inner round 0 / far side round 0.6 hole 0.3 paste-0.6 mask+0: ""(24.251,46.915) ""(27.8,53.192)
  round 0.7 / inner round 0 / far side round 0.7 hole 0.3 paste-0.7 mask+0: ""(25.126,49.79) ""(25.151,51.14) ""(29.758,53.015) ""(32.325,55.291) ""(33.701,54.14) ""(82.351,31.665) ""(88.801,37.715) ""(90.051,37.44) ""(94.25,38.916) ""(100.475,43.641)
  round 4 / inner round 0 / far side round 4 hole 2.5 paste-4.203 mask+0: ""(45.925,23.741) ""(46.15,31.166) ""(98.85,55.266) ""(103.35,58.941)
  round 3 / inner round 0 / far side round 3 hole 2 paste-3.203 mask+0: ""(67.725,53.066) ""(67.85,40.916) ""(67.95,68.241)

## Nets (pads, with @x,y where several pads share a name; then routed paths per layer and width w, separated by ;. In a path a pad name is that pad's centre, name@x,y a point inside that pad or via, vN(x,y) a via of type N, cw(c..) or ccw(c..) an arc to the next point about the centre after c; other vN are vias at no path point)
5V: C7.1 C8.1 C22.2 C36.1 pad.@27.8,59.241 pad.@46.1,63.841 R10.2 U3.38 U4.24 | length 37.1
  TOP w0.127: C7.1@27.15,59.291 27.347,59.094 27.653,59.094 pad.@27.8,59.241
  TOP w0.22: pad.@27.8,59.241 28.226,59.24 ; U3.38@29.325,59.091 28.376,59.09 ; pad.@46.1,63.841 46.151,63.79 46.151,63.092 ; U4.24@46.15,60.391 46.15,63.091 ; 28.226,59.24 27.926,59.54 27.401,59.54 C7.1@27.15,59.291 27.347,59.094 27.351,59.09 28.376,59.09 ; 28.226,59.24 28.376,59.09
  TOP w0.6: pad.@46.1,63.841 46.45,64.191 C36.1@46.7,64.191 C8.1@48.4,64.191
  TOP w0.8: R10.2@23.875,59.291 25.424,59.29 C22.2@25.425,59.291 C7.1@27.15,59.291
  BOTTOM w0.5: pad.@27.8,59.241 27.8,60.216 29.375,61.791 30.5,61.791 31.5,62.791 39.3,62.791 42.125,65.616 45.4,65.616 46.1,64.916 pad.@46.1,63.841
12V: C5.1 IC1.3 IC2.1 | length 5.4
  BOTTOM w1: IC1.3@23.525,23.766 IC1.3@23.65,23.891 ; IC2.1@23.65,28.916 IC2.1@23.65,28.791 C5.1@23.65,26.342 ; IC1.3@23.75,23.816 IC1.3@23.65,23.891 ; C5.1@23.75,26.342 C5.1@23.65,26.342 ; IC1.3@23.65,23.891 C5.1@23.65,26.342
18V: D1.2 pad.@38.276,29.29 Q1.C R14.2 | length 35.4
  TOP w0.8: R14.2@36.95,34.191 36.95,33.283 36.951,33.282 36.951,30.615 pad.@38.276,29.29
  BOTTOM w0.127: Q1.C@37.04,30.711 37.507,30.711 37.751,30.467
  BOTTOM w0.8: Q1.C@37.042,31.109 Q1.C@37.042,31.09 ; Q1.C@37.076,30.24 37.076,27.565 ; pad.@38.276,29.29 pad.@38.215,29.29 ; 38.965,31.101 38.215,31.101 38.215,31.09 ; 36.326,28.315 36.326,30.99 36.426,31.09 ; 36.326,28.315 36.662,27.979 ; 36.326,28.315 35.776,28.865 35.776,31.09 36.426,31.09 ; 36.426,31.09 Q1.C@37.042,31.09 ; 36.662,27.979 36.662,27.943 37.076,27.529 ; 36.662,27.979 37.076,27.565 ; Q1.C@37.042,31.09 37.626,31.09 ; 37.076,27.529 D1.2@38.214,26.391 38.215,27.554 ; 37.076,27.529 37.076,27.565 ; 37.076,27.565 37.112,27.529 37.751,27.529 ; 37.626,31.09 38.215,31.09 ; 37.626,31.09 37.751,30.965 37.751,30.467 37.751,27.529 ; 37.751,27.529 38.19,27.529 38.215,27.554 ; 38.215,27.554 pad.@38.215,29.29 ; 38.215,27.554 38.965,28.304 38.965,31.09 38.215,31.09 ; pad.@38.215,29.29 38.215,31.09
19VDC: J6.1 pad.@103.35,58.941 | length 2.1
  TOP w2.5: J6.1@90.875,56.991 J6.1@91.601,57.715
  BOTTOM w2.5: J6.1@90.875,56.991 J6.1@91.625,57.741
+5V: C6.1 C9.1 C14.2 C16.2 C18.1 C23.1 D3.2 IC2.3 J3.1 P1.1 P1.21 pad.@21.25,63.466 pad.@22.55,58.466 pad.@25.25,63.266 pad.@30.775,76.241 pad.@31.701,48.99 pad.@31.735,40.991 pad.@39.3,71.791 pad.@45.375,71.166 pad.@46.5,74.816 pad.@46.525,77.691 R10.1 R16.1 R17.2 R19.1 R21.1 R22.2 R24.2 R25.2 R26.2 R35.2 R36.2 R37.2 R38.1 R39.1 R41.2 R42.2 SW1.2 SW1.10 U1.8 U2.8 U3.5 | length 173.3
  TOP w0.22: U3.5@33.025,52.391 33.026,50.715 32.388,50.078 ; pad.@31.701,49.103 32.238,49.64 ; pad.@31.701,49.103 31.701,49.39 32.238,49.928 ; pad.@31.701,49.103 pad.@31.701,48.99 31.901,48.99 32.238,49.328 ; 32.238,49.328 32.388,49.478 32.388,50.078 ; 32.238,49.328 32.238,49.64 ; 32.238,49.64 32.238,49.928 ; 32.238,49.928 32.388,50.078
  TOP w0.3: pad.@31.735,40.991 32.351,40.99 ; SW1.10@32.351,41.89 32.351,40.99 ; SW1.2@34.65,39.366 34.651,39.367 34.651,40.69 34.351,40.99 32.351,40.99
  TOP w0.8: pad.@21.25,63.466 21.451,63.265 pad.@25.25,63.266 ; R10.1@22.051,59.267 22.051,58.465 pad.@22.55,58.466 ; 27.976,35.515 27.951,35.54 30.926,38.515 30.926,40.765 31.443,41.283 ; pad.@30.775,76.241 30.776,76.74 ; pad.@31.735,40.991 31.593,41.133 31.443,41.283 ; SW1.10@32.351,41.89 31.51,41.327 31.443,41.283 ; pad.@39.3,71.791 39.3,72.718 ; 39.301,72.719 39.301,73.89 40.226,74.815 pad.@46.5,74.816 ; pad.@45.375,71.166 46.326,70.215 R41.2@46.325,69.441 R39.1@47.975,69.441 ; pad.@46.525,77.691 pad.@46.525,77.691 ; R16.1@62.626,77.714 62.624,77.715 pad.@46.55,77.715 ; 30.776,76.74 31.751,77.715 ; 30.776,76.74 31.751,77.715 ; 31.751,77.715 pad.@46.526,77.715 ; pad.@46.525,77.691 pad.@46.526,77.715 ; pad.@46.525,77.691 pad.@46.55,77.715 ; pad.@46.526,77.715 pad.@46.55,77.715
  TOP w1: C6.1@27.75,34.541 28.351,35.14 ; 27.976,35.515 28.351,35.14 ; D3.2@30.832,34.016 D3.2@30.833,34.24 ; D3.2@30.876,34.24 D3.2@30.833,34.24 ; 28.351,35.14 29.251,34.24 D3.2@30.833,34.24
  BOTTOM w0.127: pad.@21.25,63.466 21.425,63.466 21.708,63.466 21.9,63.466 C18.1@21.95,63.516
  BOTTOM w0.3: R24.2@28.9,72.941 29.225,73.266 32.425,73.266 R22.2@33.35,72.341
  BOTTOM w0.8: C18.1@21.949,63.518 21.708,63.466 21.475,63.416 21.425,63.466 21.337,63.554 pad.@21.225,63.666 ; C9.1@22.825,41.666 C9.1@22.823,41.664 ; C9.1@22.825,41.664 C9.1@22.823,41.664 ; pad.@25.25,63.266 25.25,61.966 22.45,59.166 22.45,58.566 pad.@22.55,58.466 C9.1@22.55,41.664 ; C6.1@27.75,34.541 27.75,36.166 22.55,41.366 C9.1@22.55,41.664 ; R24.2@28.899,72.941 R25.2@27.15,72.941 27.149,72.941 R26.2@25.425,72.941 25.425,73.491 24.975,73.941 J3.1@23.2,73.941 22.425,73.941 21.225,72.741 pad.@21.225,63.666 ; R24.2@28.9,72.941 28.9,75.166 29.95,76.216 30.75,76.216 pad.@30.775,76.241 30.8,76.216 R21.1@31.95,76.216 ; R36.2@31.5,45.666 31.501,45.667 R36.2@31.675,45.667 ; R37.2@31.5,47.416 31.501,47.417 R37.2@31.675,47.417 ; R38.1@31.5,42.091 R38.1@31.737,42.329 ; R35.2@31.5,43.891 R35.2@31.675,43.891 ; 32.669,41.397 R38.1@31.737,42.329 ; C23.1@32.9,49.641 32.25,48.99 pad.@31.701,48.99 31.675,48.965 R37.2@31.675,47.417 ; C16.2@33.3,70.916 33.35,70.966 33.35,71.366 ; R22.2@33.35,72.341 33.35,71.366 ; 34.4,71.366 33.35,71.366 ; R19.1@39.3,72.641 pad.@39.3,71.791 39.3,71.416 39.625,71.091 40.45,71.091 ; C14.2@45.25,72.016 45.375,71.891 pad.@45.375,71.166 ; R17.2@45.375,70.366 pad.@45.375,71.166 ; pad.@46.5,74.816 pad.@46.525,74.816 ; pad.@46.525,77.691 pad.@46.525,74.816 ; pad.@21.225,63.666 21.225,63.491 pad.@21.25,63.466 pad.@21.225,63.666 ; C9.1@22.55,41.664 C9.1@22.823,41.664 ; R35.2@31.675,43.891 R36.2@31.675,45.667 ; R35.2@31.675,43.891 31.675,42.391 R38.1@31.737,42.329 ; R36.2@31.675,45.667 R37.2@31.675,47.417 ; pad.@45.375,71.166 45.85,71.166 46.525,71.841 pad.@46.525,74.816
  BOTTOM w1: 27.975,35.516 27.9,35.441 C6.1@27.9,34.541 ; IC2.3@28.65,28.791 28.875,29.016 28.875,30.666 27.95,31.591 27.95,32.341 27.9,32.391 C6.1@27.9,34.391 ; C6.1@27.9,34.391 C6.1@27.75,34.541 C6.1@27.9,34.541 ; C6.1@27.9,34.391 C6.1@27.9,34.541
+5V1: C43.2 CON1.1 CON2.1 J4.1 J4.2 J5.3 LED1.A LED2.A LED3.A LED4.A LED5.A P2.1 P2.22 pad.@93.275,30.916 | length 29.6
  TOP w0.127: P2.1@93.815,36.003 94.196,36.003 94.431,35.768 94.431,35.72
  TOP w0.8: CON2.1@80.545,44.341 CON2.1@80.545,44.341 80.546,48.215 J4.2@83.086,48.215
  BOTTOM w0.8: pad.@93.275,30.916 103.55,41.191 103.55,46.952 J5.3@103.55,49.116
AGND: C7.2 C8.2 C22.1 C24.2 C25.2 C26.2 C36.2 pad.@40,65.316 pad.@46.05,66.416 R11.2 R32.1 R33.1 R34.1 U3.26 | length 37.6
  TOP w0.22: U3.26@36.026,61.292 36.026,62.44 36.326,62.74 37.751,62.74 38.576,63.565 39.326,63.565 40.001,64.24 40.001,64.678 ; 40,64.679 pad.@40,65.316
  TOP w0.6: R11.2@23.875,61.09 R11.2@23.85,61.116 25.4,61.116 C22.1@25.425,61.091 27.15,61.091 27.575,61.091 28.626,62.14 28.626,65.69 29.601,66.665 C25.2@30.225,66.665 ; C25.2@30.225,66.666 R32.1@31.875,66.666 C24.2@33.625,66.666 R33.1@35.275,66.666 ; R33.1@35.275,66.666 C26.2@37.025,66.666 ; C26.2@37.025,66.666 37.45,66.666 37.675,66.441 R34.1@38.65,66.441 38.798,66.441 39.475,66.441 40.001,65.915 pad.@40,65.316 ; pad.@46.05,66.416 46.475,65.991 C36.2@46.7,65.991 46.702,65.991 C8.2@48.4,65.991
  BOTTOM w0.6: pad.@40,65.316 40.45,65.316 41.7,66.566 45.9,66.566 pad.@46.05,66.416
AMP_U: pad.@40.5,66.941 pad.@41.525,72.766 pad.@46.925,62.741 R31.2 U1.2 U4.23 | length 26.7
  TOP w0.22: pad.@40.5,66.941 41.526,67.967 pad.@41.526,72.765 ; U4.23@46.65,60.391 46.651,62.065 46.926,62.34 pad.@46.926,62.74
  BOTTOM w0.22: R31.2@35.8,66.616 40.175,66.616 pad.@40.5,66.941 41.025,67.466 46.6,67.466 47.208,66.858 47.208,63.061 47.163,63.016 47.163,62.979 pad.@46.925,62.741 ; U1.2@41.25,74.366 41.25,73.041 pad.@41.525,72.766
AMP_V: pad.@38.025,70.591 pad.@38.275,67.791 pad.@47.876,61.79 R30.2 U1.6 U4.22 | length 30
  TOP w0.22: pad.@38.025,70.591 38.276,70.34 pad.@38.276,67.792 ; U4.22@47.15,60.391 47.151,61.39 47.551,61.79 pad.@47.876,61.79
  BOTTOM w0.22: R30.2@33.675,66.591 33.95,66.591 34.331,66.972 35.094,67.735 38.219,67.735 pad.@38.275,67.791 38.525,68.041 46.85,68.041 47.759,67.132 47.759,61.907 pad.@47.876,61.79 ; pad.@38.025,70.591 38.35,70.591 38.725,70.216 41.5,70.216 41.75,70.466 U1.6@41.75,71.266
AMP_W: pad.@48.551,62.89 R29.1 U2.6 U4.21 | length 28.6
  TOP w0.22: U4.21@47.65,60.391 48.051,60.39 48.676,61.015 48.676,62.715 48.526,62.865 48.501,62.89 pad.@48.551,62.89
  BOTTOM w0.22: R29.1@31.95,66.591 31.95,67.216 32.425,67.691 34.25,67.691 35.225,68.666 35.7,68.666 ; U2.6@35.7,71.266 35.7,69.266 35.7,68.666 ; pad.@48.551,62.89 48.55,67.141 47.025,68.666 35.7,68.666
CAL: pad.@29.825,60.616 pad.@38.5,61.741 R47.1 U3.37 | length 11.6
  TOP w0.22: U3.37@29.325,59.591 29.325,59.938 ; 29.326,59.939 29.326,60.117 pad.@29.825,60.616 ; pad.@38.5,61.741 38.7,61.941 38.701,61.941 39.077,62.316 R47.1@39.5,62.316
  BOTTOM w0.22: pad.@29.825,60.616 30.025,60.816 30.625,60.816 31.55,61.741 pad.@38.5,61.741
DIN: P1.4 pad.@25.401,46.765 pad.@31.425,58.066 R45.1 U3.41 | length 24.3
  TOP w0.25: P1.4@21.187,45.026 22.227,45.026 23.287,43.965 24.626,43.965 25.401,44.74 pad.@25.401,46.765 ; U3.41@29.325,57.591 30.95,57.591 pad.@31.425,58.066
  BOTTOM w0.25: pad.@25.401,46.765 25.924,47.288 25.924,47.29 26.385,47.751 26.385,50.893 28.425,52.934 28.425,53.204 28.775,53.554 28.775,55.416 pad.@31.425,58.066 31.425,58.116 31.893,58.583 R45.1@32.25,58.941
DIN1: J4.4 P2.4 pad.@90.051,37.44 | length 17.4
  TOP w0.3: pad.@90.051,37.44 90.076,37.415 90.076,36.014 P2.4@90.065,36.003
  BOTTOM w0.3: J4.4@88.165,48.216 88.165,47.456 86.9,46.191 86.9,37.241 87.75,36.391 89.8,36.391 90.05,36.641 90.05,36.762 pad.@90.051,37.44
EMG: C17.1 P1.11 pad.@25.276,41.54 pad.@31.625,71.628 pad.@36.5,69.691 pad.@40.75,52.616 R23.1 R38.2 U3.15 | length 76.9
  TOP w0.22: pad.@25.276,41.54 25.54,41.276 P1.11@26.925,41.276 27.637,41.276 30.301,43.94 37.251,43.94 38.551,45.24 38.551,50.79 39.17,51.409 39.543,51.409 pad.@40.75,52.616 40.751,52.616 41.026,52.89 41.026,54.69 40.626,55.09 39.319,55.09 ; pad.@31.625,71.628 32.413,71.628 33.626,70.415 33.626,69.09 34.201,68.515 35.601,68.515 36.501,69.415 pad.@36.5,69.691 ; U3.15@38.225,55.091 39.319,55.091
  BOTTOM w0.22: pad.@25.275,41.541 25.276,41.541 29.15,41.541 R38.2@29.7,42.091 ; C17.1@31.625,70.916 pad.@31.625,71.628 R23.1@31.625,72.341 ; pad.@36.5,69.691 37,69.191 47.375,69.191 49.375,67.191 49.375,61.466 48.7,60.791 44.425,60.791 41.55,57.916 41.55,53.416 pad.@40.75,52.616
EMG1: BOOT1.2 P2.11 | length 2.7
  TOP w0.3: BOOT1.2@93.55,44.291 93.801,44.04 93.801,41.755 P2.11@93.815,41.741
EN: C29.1 R39.2 U4.30 | length 14.3
  TOP w0.25: C29.1@42.925,67.641 42.925,67.789 43.676,68.54 47.176,68.54 47.976,67.74 R39.2@47.976,67.642 ; C29.1@42.925,67.641 42.926,67.415 42.648,67.138 41.726,66.215 41.726,63.915 42.226,63.415 42.226,61.315 U4.30@43.15,60.391
F_R1: pad.@37.701,41.14 R12.1 SW1.5 | length 4.2
  TOP w0.3: SW1.5@37.65,39.366 37.701,39.417 pad.@37.701,41.14
  BOTTOM w0.3: pad.@37.701,41.14 37.899,41.14 38.875,42.116 R12.1@38.875,42.991
FR1: C10.1 pad.@39.925,54.216 R12.2 U3.14 | length 15.5
  TOP w0.22: U3.14@38.225,54.591 39.551,54.59 39.659,54.482 pad.@39.925,54.216
  BOTTOM w0.22: C10.1@37.25,44.791 R12.2@38.875,44.791 39.729,45.645 40.25,46.166 40.25,50.766 39.6,51.416 39.15,51.416 38.575,51.991 38.575,53.816 38.975,54.216 pad.@39.925,54.216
